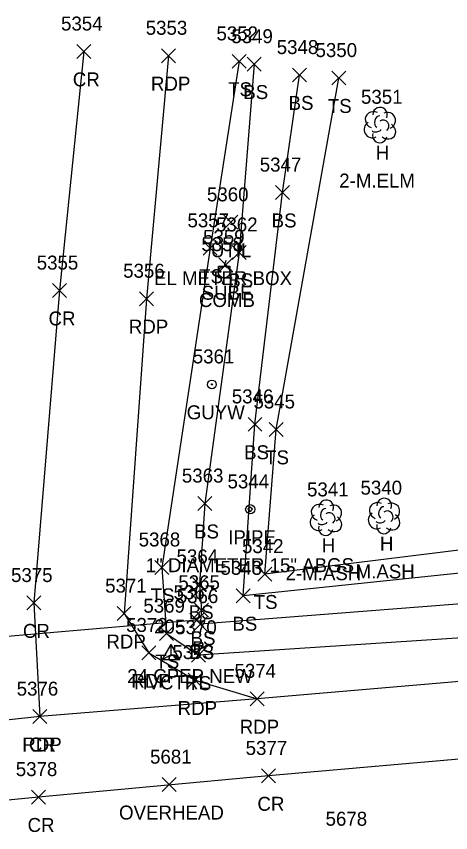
# Model space of a CAD drawing. Extents: x 1443912 to 1445411, y 621446 to 623693.
# Drawn here: x 1444412.6 to 1444474.8, y 622531.9 to 622648.8 of the extents above; entities that cross this region are included whole.
import ezdxf

# ---------------------------------------------------------------- set-up
doc = ezdxf.new("R2010")
doc.units = 0
for name, color, linetype in [('C_A', 7, 'Continuous'), ('C_I', 7, 'Continuous'), ('CPSM', 7, 'Continuous'), ('D_A', 7, 'Continuous'), ('D_C', 7, 'Continuous'), ('D_I', 7, 'Continuous'), ('D_TIC', 7, 'Continuous'), ('DCP', 7, 'Continuous'), ('L_A', 7, 'Continuous'), ('L_C', 7, 'Continuous'), ('L_I', 7, 'Continuous'), ('L_TIC', 7, 'Continuous'), ('LELB', 7, 'Continuous'), ('LTD', 7, 'Continuous'), ('M_A', 7, 'Continuous'), ('M_C', 7, 'Continuous'), ('M_I', 7, 'Continuous'), ('MPIP', 7, 'Continuous'), ('P_A', 7, 'Continuous'), ('P_I', 7, 'Continuous'), ('P_TIC', 7, 'Continuous'), ('PET', 7, 'Continuous'), ('PRC', 7, 'Continuous'), ('U_A', 7, 'Continuous'), ('U_C', 7, 'Continuous'), ('U_I', 7, 'Continuous'), ('U_TIC', 7, 'Continuous'), ('UDEFAULT', 7, 'Continuous'), ('UP', 7, 'Continuous'), ('UPGW', 7, 'Continuous')]:
    doc.layers.add(name, color=color, linetype=linetype)

msp = doc.modelspace()

# ---------------------------------------------------------------- linework, layer by layer
at = {"layer": 'CPSM'}
for p, q in [((1444433.51, 622556.68), (1444434.76, 622558.85)), ((1444436.01, 622556.68), (1444434.76, 622558.85)), ((1444434.76, 622557.41), (1444434.76, 622558.85)), ((1444433.51, 622556.68), (1444434.76, 622557.41)), ((1444434.76, 622557.41), (1444434.76, 622557.41)), ((1444434.76, 622557.41), (1444436.01, 622556.68)), ((1444433.51, 622556.68), (1444436.01, 622556.68))]:
    msp.add_line(p, q, dxfattribs=at)
at = {"layer": 'D_TIC'}
for points in [[(1444437.42, 622561.31), (1444439.42, 622563.31)], [(1444439.42, 622561.31), (1444437.42, 622563.31)]]:
    msp.add_lwpolyline(points, dxfattribs=at)
at = {"layer": 'DCP'}
msp.add_lwpolyline([(1444438.42, 622562.31), (1444389.68, 622558.12)], dxfattribs=at)
at = {"layer": 'L_TIC'}
for points in [[(1444443.51, 622641.34), (1444445.51, 622643.34)], [(1444445.51, 622641.34), (1444443.51, 622643.34)], [(1444445.65, 622640.94), (1444447.65, 622642.94)], [(1444447.65, 622640.94), (1444445.65, 622642.94)], [(1444452.14, 622639.38), (1444454.14, 622641.38)], [(1444454.14, 622639.38), (1444452.14, 622641.38)], [(1444457.79, 622638.95), (1444459.79, 622640.95)], [(1444459.79, 622638.95), (1444457.79, 622640.95)], [(1444449.71, 622622.55), (1444451.71, 622624.55)], [(1444451.71, 622622.55), (1444449.71, 622624.55)], [(1444439.36, 622614.57), (1444441.36, 622616.57)], [(1444441.36, 622614.57), (1444439.36, 622616.57)], [(1444443.5, 622613.98), (1444445.5, 622615.98)], [(1444445.5, 622613.98), (1444443.5, 622615.98)], [(1444445.77, 622589.36), (1444447.77, 622591.36)], [(1444447.77, 622589.36), (1444445.77, 622591.36)], [(1444448.81, 622588.63), (1444450.81, 622590.63)], [(1444450.81, 622588.63), (1444448.81, 622590.63)], [(1444438.6, 622578.02), (1444440.6, 622580.02)], [(1444440.6, 622578.02), (1444438.6, 622580.02)], [(1444432.42, 622568.87), (1444434.42, 622570.87)], [(1444434.42, 622568.87), (1444432.42, 622570.87)], [(1444447.17, 622567.92), (1444449.17, 622569.92)], [(1444449.17, 622567.92), (1444447.17, 622569.92)], [(1444437.84, 622566.45), (1444439.84, 622568.45)], [(1444439.84, 622566.45), (1444437.84, 622568.45)], [(1444444.08, 622564.81), (1444446.08, 622566.81)], [(1444446.08, 622564.81), (1444444.08, 622566.81)], [(1444438.1, 622562.74), (1444440.1, 622564.74)], [(1444440.1, 622562.74), (1444438.1, 622564.74)], [(1444437.94, 622560.76), (1444439.94, 622562.76)], [(1444439.94, 622560.76), (1444437.94, 622562.76)], [(1444437.94, 622560.76), (1444439.94, 622562.76)], [(1444439.94, 622560.76), (1444437.94, 622562.76)], [(1444433.09, 622559.39), (1444435.09, 622561.39)], [(1444435.09, 622559.39), (1444433.09, 622561.39)], [(1444437.69, 622556.3), (1444439.69, 622558.3)], [(1444439.69, 622556.3), (1444437.69, 622558.3)], [(1444437.69, 622556.3), (1444439.69, 622558.3)], [(1444439.69, 622556.3), (1444437.69, 622558.3)]]:
    msp.add_lwpolyline(points, dxfattribs=at)
at = {"layer": 'LELB'}
for points in [[(1444444.51, 622642.34), (1444440.36, 622615.57), (1444433.42, 622569.87), (1444434.09, 622560.39), (1444438.69, 622557.3)], [(1444446.65, 622641.94), (1444444.5, 622614.98), (1444439.6, 622579.02), (1444438.84, 622567.45), (1444439.1, 622563.74), (1444438.94, 622561.76)], [(1444506.9, 622571.66), (1444486.15, 622570.08), (1444445.08, 622565.81), (1444446.77, 622590.36), (1444450.71, 622623.55), (1444453.14, 622640.38)], [(1444527.16, 622562.76), (1444530.38, 622567.98), (1444529.13, 622577.46), (1444519.97, 622577.24), (1444507.22, 622576.8), (1444485.65, 622573.52), (1444448.17, 622568.92), (1444449.81, 622589.63), (1444458.79, 622639.95)], [(1444506.9, 622571.66), (1444525.13, 622572.88), (1444524.97, 622569.84), (1444507.94, 622567.17), (1444486.73, 622565.49), (1444438.94, 622561.76)], [(1444527.16, 622562.76), (1444487.33, 622560.48), (1444438.69, 622557.3)]]:
    msp.add_lwpolyline(points, dxfattribs=at)
at = {"layer": 'LTD'}
for p, q in [((1444464.64, 622633.26), (1444464.64, 622633.26)), ((1444464.64, 622633.26), (1444464.64, 622633.26)), ((1444456.91, 622577.04), (1444456.91, 622577.04)), ((1444456.91, 622577.04), (1444456.91, 622577.04)), ((1444465.23, 622577.29), (1444465.23, 622577.29)), ((1444465.23, 622577.29), (1444465.23, 622577.29))]:
    msp.add_line(p, q, dxfattribs=at)
for centre in [(1444464.68, 622634.7), (1444456.96, 622578.47), (1444465.28, 622578.73)]:
    msp.add_arc(centre, 1.05, 335.5272, 180.9563, dxfattribs=at)
for centre, major_axis, ratio, start_param, end_param in [((1444463.85, 622633.93), (1.21, -0.51), 0.895232, 1.570796, 4.712389), ((1444465.68, 622633.85), (-1.14, -0.48), 0.949671, 1.570796, 4.712389), ((1444464.43, 622633.72), (-0.208, -0.792), 0.645439, 3.141593, 6.283185), ((1444465.14, 622633.1), (-0.5, 0.667), 0.989748, 3.141593, 6.283185), ((1444463.55, 622632.55), (0.58, -1.04), 0.959034, 3.141593, 6.283185), ((1444465.64, 622632.43), (-1.09, 0.79), 0.841452, 1.570796, 4.712389), ((1444464.64, 622631.76), (0.26, 1.06), 0.942809, 1.570796, 4.712389), ((1444464.18, 622632.51), (-0.625, -0.083), 0.423636, 0, 3.141593), ((1444456.12, 622577.7), (1.21, -0.51), 0.895232, 1.570796, 4.712389), ((1444464.44, 622577.96), (1.21, -0.51), 0.895232, 1.570796, 4.712389), ((1444466.27, 622577.88), (-1.14, -0.48), 0.949671, 1.570796, 4.712389), ((1444456.7, 622577.5), (-0.208, -0.792), 0.645439, 3.141593, 6.283185), ((1444457.95, 622577.62), (-1.14, -0.48), 0.949671, 1.570796, 4.712389), ((1444465.02, 622577.75), (-0.208, -0.792), 0.645439, 3.141593, 6.283185), ((1444465.73, 622577.13), (-0.5, 0.667), 0.989748, 3.141593, 6.283185), ((1444455.83, 622576.33), (0.58, -1.04), 0.959034, 3.141593, 6.283185), ((1444457.41, 622576.87), (-0.5, 0.667), 0.989748, 3.141593, 6.283185), ((1444457.91, 622576.2), (-1.09, 0.79), 0.841452, 1.570796, 4.712389), ((1444464.15, 622576.59), (0.58, -1.04), 0.959034, 3.141593, 6.283185), ((1444466.23, 622576.46), (-1.09, 0.79), 0.841452, 1.570796, 4.712389), ((1444456.91, 622575.54), (0.26, 1.06), 0.942809, 1.570796, 4.712389), ((1444456.45, 622576.29), (-0.625, -0.083), 0.423636, 0, 3.141593), ((1444465.23, 622575.79), (0.26, 1.06), 0.942809, 1.570796, 4.712389), ((1444464.77, 622576.54), (-0.625, -0.083), 0.423636, 0, 3.141593)]:
    msp.add_ellipse(centre, major_axis=major_axis, ratio=ratio, start_param=start_param, end_param=end_param, dxfattribs=at)
at = {"layer": 'MPIP'}
msp.add_lwpolyline([(1444446.43, 622578.19), (1444446.1, 622578.52), (1444445.76, 622578.19), (1444446.1, 622577.85)], close=True, dxfattribs=at)
msp.add_circle((1444446.1, 622578.19), 0.667, dxfattribs=at)
at = {"layer": 'P_TIC'}
for points in [[(1444421.25, 622642.75), (1444423.25, 622644.75)], [(1444423.25, 622642.75), (1444421.25, 622644.75)], [(1444433.38, 622642.14), (1444435.38, 622644.14)], [(1444435.38, 622642.14), (1444433.38, 622644.14)], [(1444417.77, 622608.52), (1444419.77, 622610.52)], [(1444419.77, 622608.52), (1444417.77, 622610.52)], [(1444430.21, 622607.35), (1444432.21, 622609.35)], [(1444432.21, 622607.35), (1444430.21, 622609.35)], [(1444414.09, 622563.78), (1444416.09, 622565.78)], [(1444416.09, 622563.78), (1444414.09, 622565.78)], [(1444427.01, 622562.26), (1444429.01, 622564.26)], [(1444429.01, 622562.26), (1444427.01, 622564.26)], [(1444430.57, 622556.63), (1444432.57, 622558.63)], [(1444432.57, 622556.63), (1444430.57, 622558.63)], [(1444437.2, 622552.74), (1444439.2, 622554.74)], [(1444439.2, 622552.74), (1444437.2, 622554.74)], [(1444446.09, 622550.06), (1444448.09, 622552.06)], [(1444448.09, 622550.06), (1444446.09, 622552.06)], [(1444446.09, 622550.06), (1444448.09, 622552.06)], [(1444448.09, 622550.06), (1444446.09, 622552.06)], [(1444414.95, 622547.51), (1444416.95, 622549.51)], [(1444416.95, 622547.51), (1444414.95, 622549.51)], [(1444414.95, 622547.51), (1444416.95, 622549.51)], [(1444416.95, 622547.51), (1444414.95, 622549.51)], [(1444447.69, 622539.02), (1444449.69, 622541.02)], [(1444449.69, 622539.02), (1444447.69, 622541.02)], [(1444414.77, 622535.99), (1444416.77, 622537.99)], [(1444416.77, 622535.99), (1444414.77, 622537.99)]]:
    msp.add_lwpolyline(points, dxfattribs=at)
at = {"layer": 'PET'}
for points in [[(1444434.38, 622643.14), (1444431.21, 622608.35), (1444428.01, 622563.26), (1444431.57, 622557.63), (1444438.2, 622553.74), (1444447.09, 622551.06)], [(1444727.75, 622590.13), (1444719.16, 622580.43), (1444710.14, 622575.73), (1444699.63, 622573.2), (1444681.85, 622571.77), (1444667.76, 622571.14), (1444650.5, 622569.81), (1444612.69, 622566.37), (1444582.45, 622563.73), (1444564.11, 622562), (1444525.39, 622558.42), (1444488.31, 622554.6), (1444447.09, 622551.06), (1444415.95, 622548.51), (1444383.77, 622544.98), (1444340.89, 622540.77), (1444296.33, 622536.74), (1444247.14, 622532.77)]]:
    msp.add_lwpolyline(points, dxfattribs=at)
at = {"layer": 'PRC'}
for points in [[(1444422.25, 622643.75), (1444418.77, 622609.52), (1444415.09, 622564.78), (1444415.95, 622548.51)], [(1444719.77, 622561.99), (1444681.72, 622559.72), (1444650.83, 622557.58), (1444613.8, 622554.84), (1444583.05, 622552.28), (1444545.98, 622548.57), (1444490.19, 622543.66), (1444448.69, 622540.02), (1444415.77, 622536.99), (1444385.19, 622533.95), (1444342.42, 622530.03), (1444296.8, 622526.08), (1444247.95, 622521.6), (1444210.22, 622518.45), (1444165.33, 622514.18), (1444110.47, 622509.68), (1444063.9, 622505.59), (1444012.84, 622501.59), (1443966.33, 622497.17), (1443919.63, 622492.61)]]:
    msp.add_lwpolyline(points, dxfattribs=at)
at = {"layer": 'U_TIC'}
for points in [[(1444441.6, 622612.2), (1444443.6, 622614.2)], [(1444443.6, 622612.2), (1444441.6, 622614.2)], [(1444433.48, 622537.77), (1444435.48, 622539.77)], [(1444435.48, 622537.77), (1444433.48, 622539.77)]]:
    msp.add_lwpolyline(points, dxfattribs=at)
at = {"layer": 'UDEFAULT'}
for points in [[(1444442.29, 622618.29), (1444444.29, 622620.29)], [(1444444.29, 622618.29), (1444442.29, 622620.29)]]:
    msp.add_lwpolyline(points, dxfattribs=at)
at = {"layer": 'UP'}
for p, q in [((1444441.52, 622611.32), (1444441.52, 622612.99)), ((1444441.52, 622612.99), (1444443.18, 622612.99)), ((1444442.6, 622613.82), (1444442.35, 622612.99)), ((1444443.18, 622612.99), (1444443.18, 622611.32)), ((1444442.35, 622612.16), (1444442.35, 622612.16)), ((1444443.18, 622611.32), (1444441.52, 622611.32)), ((1444442.1, 622610.49), (1444442.35, 622611.32))]:
    msp.add_line(p, q, dxfattribs=at)
msp.add_circle((1444442.35, 622612.16), 0.833, dxfattribs=at)
at = {"layer": 'UPGW'}
for radius in [0.625, 0.0833]:
    msp.add_circle((1444440.6, 622596.08), radius, dxfattribs=at)

# ---------------------------------------------------------------- texts
at = {"layer": 'C_A'}
msp.add_text('HVCTRL', height=2, dxfattribs=at).set_placement((1444429.45, 622552.41))
at = {"layer": 'C_I'}
msp.add_text('205', height=2, dxfattribs=at).set_placement((1444432.32, 622560.41))
at = {"layer": 'D_A'}
msp.add_text('P', height=2, dxfattribs=at).set_placement((1444437.8, 622557.31))
at = {"layer": 'D_C'}
msp.add_text('24 CPEP NEW', height=2, dxfattribs=at).set_placement((1444428.47, 622553.31))
at = {"layer": 'D_I'}
msp.add_text('5367', height=2, dxfattribs=at).set_placement((1444435.11, 622565.31))
at = {"layer": 'L_A'}
for s, p in [('TS', (1444442.92, 622637.34)), ('BS', (1444445.09, 622636.94)), ('BS', (1444451.58, 622635.38)), ('TS', (1444457.2, 622634.95)), ('H', (1444464.07, 622628.26)), ('BS', (1444449.15, 622618.55)), ('TS', (1444438.77, 622610.57)), ('BS', (1444442.94, 622609.98)), ('BS', (1444445.21, 622585.36)), ('TS', (1444448.22, 622584.63)), ('BS', (1444438.04, 622574.02)), ('H', (1444456.34, 622572.04)), ('H', (1444464.66, 622572.29)), ('TS', (1444431.83, 622564.87)), ('TS', (1444446.58, 622563.92)), ('BS', (1444437.28, 622562.45)), ('BS', (1444443.53, 622560.81)), ('BS', (1444437.54, 622558.74)), ('BS', (1444437.38, 622556.76)), ('BS', (1444437.38, 622556.76)), ('TS', (1444432.5, 622555.39)), ('TS', (1444437.1, 622552.3)), ('TS', (1444437.1, 622552.3))]:
    msp.add_text(s, height=2, dxfattribs=at).set_placement(p)
at = {"layer": 'L_C'}
for s, p in [('2-M.ELM', (1444458.83, 622624.26)), ('2-M.ASH', (1444451.15, 622568.04)), ('M.ASH', (1444461.18, 622568.29))]:
    msp.add_text(s, height=2, dxfattribs=at).set_placement(p)
at = {"layer": 'L_I'}
for s, p in [('5352', (1444441.25, 622645.34)), ('5349', (1444443.38, 622644.94)), ('5348', (1444449.88, 622643.38)), ('5350', (1444455.44, 622642.95)), ('5351', (1444461.95, 622636.26)), ('5347', (1444447.45, 622626.55)), ('5357', (1444437.1, 622618.57)), ('5362', (1444441.19, 622617.98)), ('5346', (1444443.45, 622593.36)), ('5345', (1444446.55, 622592.63)), ('5363', (1444436.3, 622582.02)), ('5341', (1444454.22, 622580.04)), ('5340', (1444461.88, 622580.29)), ('5368', (1444430.11, 622572.87)), ('5342', (1444444.91, 622571.92)), ('5364', (1444435.54, 622570.45)), ('5343', (1444441.82, 622568.81)), ('5365', (1444435.79, 622566.74)), ('5366', (1444435.57, 622564.76)), ('5366', (1444435.57, 622564.76)), ('5369', (1444430.78, 622563.39)), ('5370', (1444435.34, 622560.3)), ('5370', (1444435.34, 622560.3))]:
    msp.add_text(s, height=2, dxfattribs=at).set_placement(p)
at = {"layer": 'M_A'}
msp.add_text('IPIPE', height=2, dxfattribs=at).set_placement((1444442.93, 622573.19))
at = {"layer": 'M_C'}
msp.add_text('1" DIAMETER 15" ABGS', height=2, dxfattribs=at).set_placement((1444431.12, 622569.19))
at = {"layer": 'M_I'}
msp.add_text('5344', height=2, dxfattribs=at).set_placement((1444442.84, 622581.19))
at = {"layer": 'P_A'}
for s, p in [('CR', (1444420.68, 622638.75)), ('RDP', (1444431.87, 622638.14)), ('CR', (1444417.2, 622604.52)), ('RDP', (1444428.7, 622603.35)), ('CR', (1444413.53, 622559.78)), ('RDP', (1444425.49, 622558.26)), ('RDP', (1444429.05, 622552.63)), ('RDP', (1444435.69, 622548.74)), ('RDP', (1444444.58, 622546.06)), ('RDP', (1444444.58, 622546.06)), ('RDP', (1444413.44, 622543.51)), ('CR', (1444414.39, 622543.51)), ('CR', (1444447.12, 622535.02)), ('CR', (1444414.2, 622531.99))]:
    msp.add_text(s, height=2, dxfattribs=at).set_placement(p)
at = {"layer": 'P_I'}
for s, p in [('5354', (1444418.99, 622646.75)), ('5353', (1444431.12, 622646.14)), ('5355', (1444415.51, 622612.52)), ('5356', (1444427.89, 622611.35)), ('5375', (1444411.83, 622567.78)), ('5371', (1444425.31, 622566.26)), ('5372', (1444428.31, 622560.63)), ('5373', (1444434.94, 622556.74)), ('5374', (1444443.83, 622554.06)), ('5374', (1444443.83, 622554.06)), ('5376', (1444412.64, 622551.51)), ('5376', (1444412.64, 622551.51)), ('5377', (1444445.43, 622543.02)), ('5378', (1444412.51, 622539.99)), ('5678', (1444456.88, 622532.88))]:
    msp.add_text(s, height=2, dxfattribs=at).set_placement(p)
at = {"layer": 'U_A'}
for s, p in [('UTIL', (1444440.45, 622614.29)), ('SUBE', (1444439.13, 622608.2)), ('COMB', (1444438.74, 622607.16)), ('GUYW', (1444436.99, 622591.08)), ('OVERHEAD', (1444427.3, 622533.77))]:
    msp.add_text(s, height=2, dxfattribs=at).set_placement(p)
at = {"layer": 'U_C'}
msp.add_text('EL METER BOX', height=2, dxfattribs=at).set_placement((1444432.31, 622610.29))
at = {"layer": 'U_I'}
for s, p in [('5360', (1444439.89, 622622.29)), ('5359', (1444439.33, 622616.2)), ('5358', (1444439.09, 622615.16)), ('5361', (1444437.86, 622599.08)), ('5681', (1444431.74, 622541.77))]:
    msp.add_text(s, height=2, dxfattribs=at).set_placement(p)

doc.saveas('drawing.dxf')
